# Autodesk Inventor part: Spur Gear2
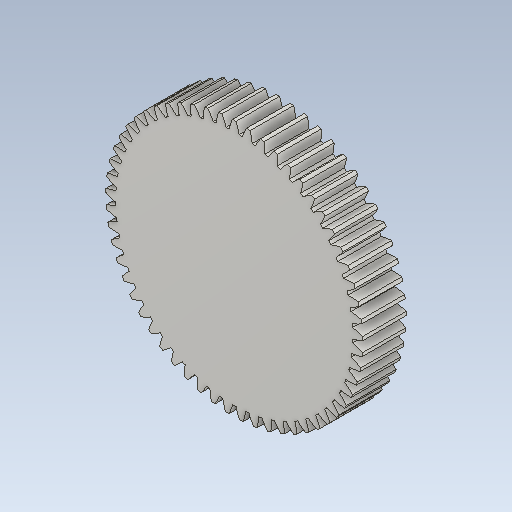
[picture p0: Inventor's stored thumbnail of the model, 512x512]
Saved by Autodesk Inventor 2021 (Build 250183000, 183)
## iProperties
Created: 2026-10
Part Number: Spur Gear2
Material: Steel
Document SubType Name: Modeling
Designer: hp
Categories: <?xml version="1.0" encoding="UTF-16"?> <MemberInstance><Categories><FamilyTemplate><FamilyTemplateParameter ValueType="xs:double" Id="1" ObjectReferenceKey="da
Density: 1 g/cm^3
Appearance: Steel
CustomPartVersion: 1
Author: hp
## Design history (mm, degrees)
sketch "Sketch1"
  geometry: C1 r 59 at (0, 0)
  constraints: 1 centre point
  dimensions: "d0" = 118 diameter of C1 (= da_da)
extrude "Extrusion1" new body sketch "Sketch1" distance "d1" = 20 (= da_b); taper "d2" = 0 deg
workplane "Work Plane2"
sketch "Sketch2"
  geometry: C1 r 59 at (0, 0) reference; C2 r 57 at (0, 0)
  constraints: 1 centre point, 1 coincident
  dimensions: "d3" = 114 diameter of C2 (= da_d)
feature "Pitch Diameter" sketch "Sketch2" dims "d4" = 10, "d5" = 0
workplane "Work Plane8"
workplane "Work Plane9"
feature "Spur Gear" dims "da_b" = 20, "da_d" = 114, "da_aw" = 80, "da_da" = 118, "da_df" = 109, "da_dw" = 114, angle "da_beta" = 0 deg, "da_lefttooth" = 0, "da_righttooth" = 0
body "Solid1"
body "Srf1"
other parameters: "d17" = 0, "d34" = 0.55116 (computed from da_z), "d39" = 0, "d41" = 0, "d47" = 0, "d48" = 0
